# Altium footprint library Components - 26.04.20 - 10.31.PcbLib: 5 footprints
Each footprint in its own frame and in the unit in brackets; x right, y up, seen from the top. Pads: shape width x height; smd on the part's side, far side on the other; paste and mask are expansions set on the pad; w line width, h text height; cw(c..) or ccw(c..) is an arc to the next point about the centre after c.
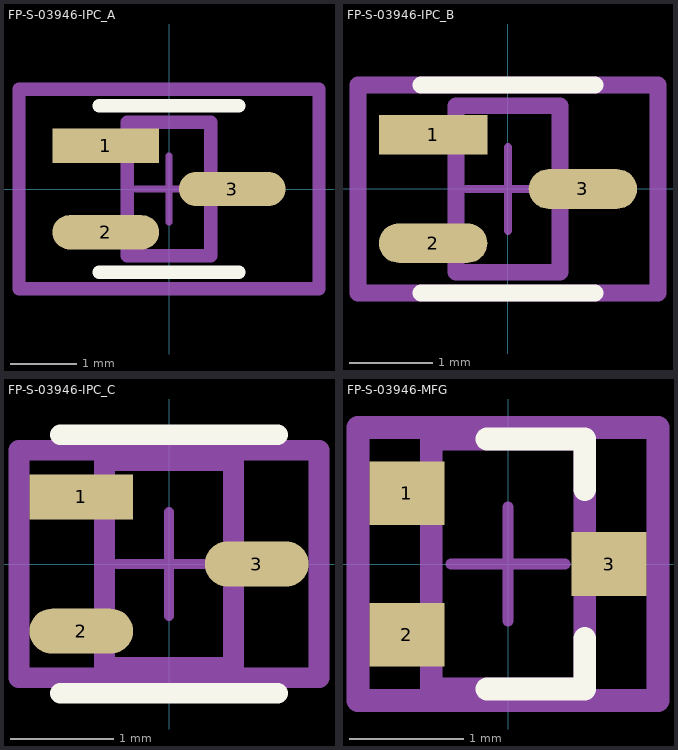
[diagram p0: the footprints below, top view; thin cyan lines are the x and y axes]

## FP-S-03946-IPC_A [mm]
pads (3):
  rect 1.604x0.516 smd paste+0 mask+0: 1(-0.95,0.65)
  rrect100% 1.604x0.516 smd paste+0 mask+0: 2(-0.95,-0.65) 3(0.95,0)
Top Overlay:
  lines w0.2: -1.05,-1.25 1.05,-1.25 ; -1.05,1.25 1.05,1.25
Mechanical 5:
  lines w0.2: -2.252,-1.5 2.252,-1.5 2.252,1.5 -2.252,1.5 -2.252,-1.5
  text ".Designator" at 0,0 h1
Mechanical 13:
  lines w0.2: -0.625,-1 0.625,-1 0.625,1 -0.625,1 -0.625,-1
Mechanical 15:
  lines w0.2: -2.252,-1.5 2.252,-1.5 2.252,1.5 -2.252,1.5 -2.252,-1.5
Mechanical 16:
  lines w0.1: -0.5,0 0.5,0 ; 0,-0.5 0,0.5
3D body "Trans_Vishay_SI1308EDL-T1-GE3_eec.STEP": height 0.25, standoff 0, extent -2.252,-1.5 2.252,1.5

## FP-S-03946-IPC_B [mm]
pads (3):
  rect 1.304x0.476 smd paste+0 mask+0: 1(-0.9,0.65)
  rrect100% 1.304x0.476 smd paste+0 mask+0: 2(-0.9,-0.65) 3(0.9,0)
Top Overlay:
  lines w0.2: -1.05,-1.25 1.05,-1.25 ; -1.05,1.25 1.05,1.25
Mechanical 5:
  lines w0.2: -1.802,-1.25 1.802,-1.25 1.802,1.25 -1.802,1.25 -1.802,-1.25
  text ".Designator" at 0,0 h1
Mechanical 13:
  lines w0.2: -0.625,-1 0.625,-1 0.625,1 -0.625,1 -0.625,-1
Mechanical 15:
  lines w0.2: -1.802,-1.25 1.802,-1.25 1.802,1.25 -1.802,1.25 -1.802,-1.25
Mechanical 16:
  lines w0.1: -0.5,0 0.5,0 ; 0,-0.5 0,0.5
3D body "Trans_Vishay_SI1308EDL-T1-GE3_eec.STEP": height 0.25, standoff 0, extent -1.802,-1.25 1.802,1.25

## FP-S-03946-IPC_C [mm]
pads (3):
  rect 1.004x0.436 smd paste+0 mask+0: 1(-0.85,0.65)
  rrect100% 1.004x0.436 smd paste+0 mask+0: 2(-0.85,-0.65) 3(0.85,0)
Top Overlay:
  lines w0.2: -1.05,-1.25 1.05,-1.25 ; -1.05,1.25 1.05,1.25
Mechanical 5:
  lines w0.2: -1.452,-1.1 1.452,-1.1 1.452,1.1 -1.452,1.1 -1.452,-1.1
  text ".Designator" at 0,0 h1
Mechanical 13:
  lines w0.2: -0.625,-1 0.625,-1 0.625,1 -0.625,1 -0.625,-1
Mechanical 15:
  lines w0.2: -1.452,-1.1 1.452,-1.1 1.452,1.1 -1.452,1.1 -1.452,-1.1
Mechanical 16:
  lines w0.1: -0.5,0 0.5,0 ; 0,-0.5 0,0.5
3D body "Trans_Vishay_SI1308EDL-T1-GE3_eec.STEP": height 0.25, standoff 0, extent -1.452,-1.1 1.452,1.1

## FP-S-03946-MFG [mil]
pads (3):
  rect 26x22 smd paste+0 mask+0: 1(-35,24.5) 2(-35,-24.5) 3(35,0)
Top Overlay:
  lines w7.87: -7.24,-43.31 26.57,-43.31 26.57,-25.76 ; -7.24,43.31 26.57,43.31 26.57,25.76
Mechanical 5:
  lines w7.87: -51.94,-47.24 51.94,-47.24 51.94,47.24 -51.94,47.24 -51.94,-47.24
  text ".Designator" at 0,0 h39.37
Mechanical 13:
  lines w7.87: -26.57,-43.31 26.57,-43.31 26.57,43.31 -26.57,43.31 -26.57,-43.31
Mechanical 15:
  lines w7.87: -51.94,-47.24 51.94,-47.24 51.94,47.24 -51.94,47.24 -51.94,-47.24
Mechanical 16:
  lines w3.94: -19.68,0 19.68,0 ; 0,-19.68 0,19.68
3D body "Trans_Vishay_SI1308EDL-T1-GE3_eec.STEP": height 10, standoff 0, extent -51.94,-47.24 51.94,47.24

## PCBComponent_1 [mil]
